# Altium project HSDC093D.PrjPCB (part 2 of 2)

## Sheet HSDC093D_720.SchDoc
size 431 x 279 mm; Date: Not shown in title block; ApprovedBy: Not shown in title block; CheckedBy: Not shown in title block; Author: Not shown in title block; CompanyName: Not shown in title block; Engineer: Not shown in title block; Organization: Not shown in title block; Address1: Not shown in title block; Address2: Not shown in title block; Address3: Not shown in title block; Address4: Not shown in title block; DocumentNumber: 2; Revision: Use project parameter SCH_Rev; SheetNumber: 2; SheetTotal: 5; PageSetup: Record=PageOptions¦CenterHorizontal=True¦CenterVertical=True¦PrintScale=1.00¦XCorrection=1.00¦YCorrection=1.00¦PrintKind=0¦BorderSize=5000000¦LeftOffset=0¦BottomOffset=0¦Orientation=2¦PaperLength=1000¦PaperWidth=1000¦Scale=100¦PaperSource=15¦PrintQuality=600¦MediaType=1¦DitherType=10¦PaperKind=Letter¦PrintScaleMode=1
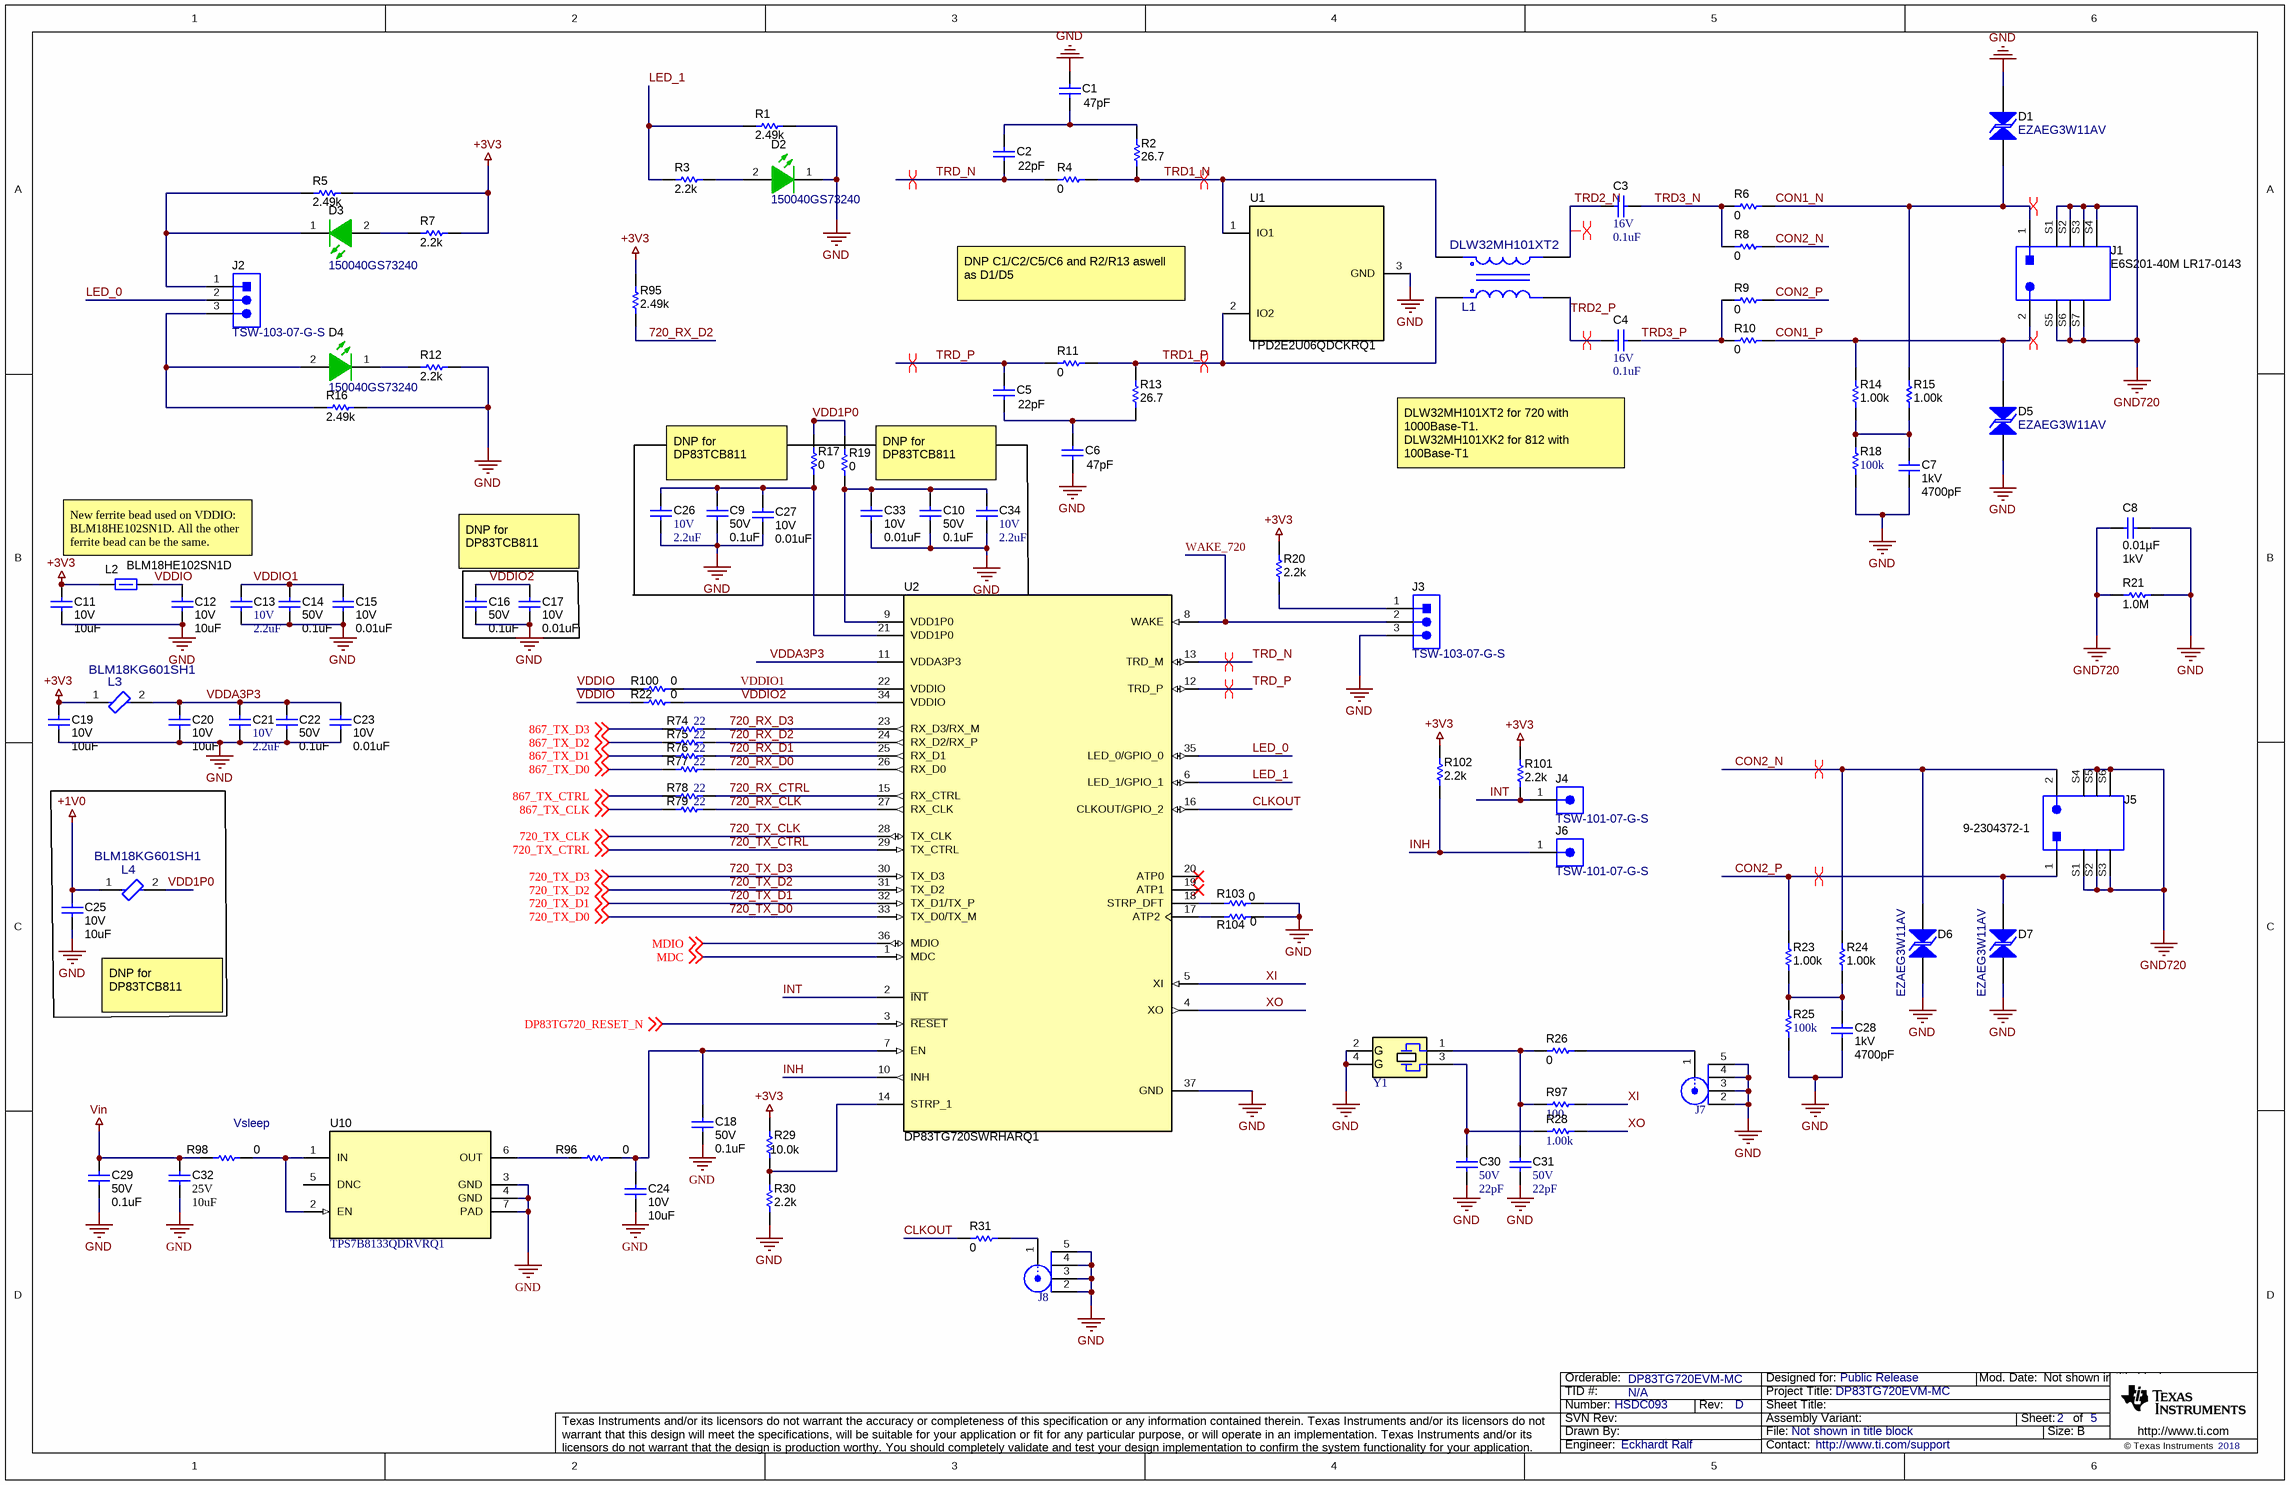
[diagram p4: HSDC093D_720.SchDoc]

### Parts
C1  ValueDisplayed: 47pF  [0402]  (hidden comment: GRM1555C1H470FA01D)
C2  ValueDisplayed: 22pF  [0402]  (hidden comment: GRM1555C1H220FA01D)
C3  VDC_V: 16V  ValueDisplayed: 0.1uF  [0402]  (hidden comment: 0402YC104KAT2A)
C4  VDC_V: 16V  ValueDisplayed: 0.1uF  [0402]  (hidden comment: 0402YC104KAT2A)
C5  ValueDisplayed: 22pF  [0402]  (hidden comment: GRM1555C1H220FA01D)
C6  ValueDisplayed: 47pF  [0402]  (hidden comment: GRM1555C1H470FA01D)
C7  VDC_V: 1kV  ValueDisplayed: 4700pF  [1206]  (hidden comment: GRM31BR73A472KW01L)
C8  ValueDisplayed: 0.01µF  VDC_V: 1kV  [1206]  (hidden comment: C1206X103KDRAC7800)
C9  VDC_V: 50V  ValueDisplayed: 0.1uF  [0402]  (hidden comment: C1005X5R1H104K050BB)
C10  VDC_V: 50V  ValueDisplayed: 0.1uF  [0402]  (hidden comment: C1005X5R1H104K050BB)
C11  VDC_V: 10V  ValueDisplayed: 10uF  [0402]  (hidden comment: GRM155R61A106ME11)
C12  VDC_V: 10V  ValueDisplayed: 10uF  [0402]  (hidden comment: GRM155R61A106ME11)
C13  VDC_V: 10V  ValueDisplayed: 2.2uF  [0402]  (hidden comment: C1005X5R1A225K050BC)
C14  VDC_V: 50V  ValueDisplayed: 0.1uF  [0402]  (hidden comment: C1005X5R1H104K050BB)
C15  VDC_V: 10V  ValueDisplayed: 0.01uF  [0402]  (hidden comment: GRM155R61A103KA01D)
C16  VDC_V: 50V  ValueDisplayed: 0.1uF  [0402]  (hidden comment: C1005X5R1H104K050BB)
C17  VDC_V: 10V  ValueDisplayed: 0.01uF  [0402]  (hidden comment: GRM155R61A103KA01D)
C18  VDC_V: 50V  ValueDisplayed: 0.1uF  [0402]  (hidden comment: C1005X5R1H104K050BB)
C19  VDC_V: 10V  ValueDisplayed: 10uF  [0402]  (hidden comment: GRM155R61A106ME11)
C20  VDC_V: 10V  ValueDisplayed: 10uF  [0402]  (hidden comment: GRM155R61A106ME11)
C21  VDC_V: 10V  ValueDisplayed: 2.2uF  [0402]  (hidden comment: C1005X5R1A225K050BC)
C22  VDC_V: 50V  ValueDisplayed: 0.1uF  [0402]  (hidden comment: C1005X5R1H104K050BB)
C23  VDC_V: 10V  ValueDisplayed: 0.01uF  [0402]  (hidden comment: GRM155R61A103KA01D)
C24  VDC_V: 10V  ValueDisplayed: 10uF  [0402]  (hidden comment: GRM155R61A106ME11)
C25  VDC_V: 10V  ValueDisplayed: 10uF  [0402]  (hidden comment: GRM155R61A106ME11)
C26  VDC_V: 10V  ValueDisplayed: 2.2uF  [0402]  (hidden comment: C1005X5R1A225K050BC)
C27  VDC_V: 10V  ValueDisplayed: 0.01uF  [0402]  (hidden comment: GRM155R61A103KA01D)
C28  VDC_V: 1kV  ValueDisplayed: 4700pF  [1206]  (hidden comment: GRM31BR73A472KW01L)
C29  VDC_V: 50V  ValueDisplayed: 0.1uF  [0402]  (hidden comment: C1005X5R1H104K050BB)
C30  VDC_V: 50V  ValueDisplayed: 22pF  [0402]  (hidden comment: GRM1555C1H220FA01D)
C31  VDC_V: 50V  ValueDisplayed: 22pF  [0402]  (hidden comment: GRM1555C1H220FA01D)
C32  VDC_V: 25V  ValueDisplayed: 10uF  [0603]  (hidden comment: C1608X5R1E106M080AC)
C33  VDC_V: 10V  ValueDisplayed: 0.01uF  [0402]  (hidden comment: GRM155R61A103KA01D)
C34  VDC_V: 10V  ValueDisplayed: 2.2uF  [0402]  (hidden comment: C1005X5R1A225K050BC)
D1  EZAEG3W11AV  [0603]
D2  150040GS73240  [WL-SMCC_0402_Green]
D3  150040GS73240  [WL-SMCC_0402_Green]
D4  150040GS73240  [WL-SMCC_0402_Green]
D5  EZAEG3W11AV  [0603]
D6  EZAEG3W11AV  [0603]
D7  EZAEG3W11AV  [0603]
J1  E6S201-40M LR17-0143  [Rosenberger_E6S201-40M_LR17-0143]
J2  TSW-103-07-G-S  [TSW-103-07-G-S]
J3  TSW-103-07-G-S  [TSW-103-07-G-S]
J4  TSW-101-07-G-S  [TSW-101-07-G-S]
J5  9-2304372-1  [TE_1PORT_B1-B]
J6  TSW-101-07-G-S  [TSW-101-07-G-S]
J7  901-144-8RFX  [AMPHENOL_901-144-8RFX]  (value not drawn)
J8  901-144-8RFX  [AMPHENOL_901-144-8RFX]  (value not drawn)
L1  DLW32MH101XT2  [FP-DLW32MH101XT2_1210-MFG]
L2  BLM18HE102SN1D  [0603]
L3  BLM18KG601SH1  [FP-BLM18KG601SH1_0603 (1608 Metric)-MFG]
L4  BLM18KG601SH1  [FP-BLM18KG601SH1_0603 (1608 Metric)-MFG]
R1  ValueDisplayed: 2.49k  [0402]  (hidden comment: CRCW04022K49FKED)
R2  ValueDisplayed: 26.7  [0402]  (hidden comment: CRCW040226R7FKED)
R3  ValueDisplayed: 2.2k  [0402]  (hidden comment: CRCW04022K20JNED)
R4  ValueDisplayed: 0  [0402]  (hidden comment: CRCW04020000Z0EDHP)
R5  ValueDisplayed: 2.49k  [0402]  (hidden comment: CRCW04022K49FKED)
R6  ValueDisplayed: 0  [0402]  (hidden comment: CRCW04020000Z0EDHP)
R7  ValueDisplayed: 2.2k  [0402]  (hidden comment: CRCW04022K20JNED)
R8  ValueDisplayed: 0  [0402]  (hidden comment: CRCW04020000Z0EDHP)
R9  ValueDisplayed: 0  [0402]  (hidden comment: CRCW04020000Z0EDHP)
R10  ValueDisplayed: 0  [0402]  (hidden comment: CRCW04020000Z0EDHP)
R11  ValueDisplayed: 0  [0402]  (hidden comment: CRCW04020000Z0EDHP)
R12  ValueDisplayed: 2.2k  [0402]  (hidden comment: CRCW04022K20JNED)
R13  ValueDisplayed: 26.7  [0402]  (hidden comment: CRCW040226R7FKED)
R14  ValueDisplayed: 1.00k  [0805_HV]  (hidden comment: ERJ-P06F1001V)
R15  ValueDisplayed: 1.00k  [0805_HV]  (hidden comment: ERJ-P06F1001V)
R16  ValueDisplayed: 2.49k  [0402]  (hidden comment: CRCW04022K49FKED)
R17  ValueDisplayed: 0  [0402]  (hidden comment: CRCW04020000Z0EDHP)
R18  ValueDisplayed: 100k  [0805_HV]  (hidden comment: CRCW08051M00JNEA)
R19  ValueDisplayed: 0  [0402]  (hidden comment: CRCW04020000Z0EDHP)
R20  ValueDisplayed: 2.2k  [0402]  (hidden comment: CRCW04022K20JNED)
R21  ValueDisplayed: 1.0M  [1206]  (hidden comment: CRCW12061M00JNEA)
R22  ValueDisplayed: 0  [0402]  (hidden comment: CRCW04020000Z0EDHP)
R23  ValueDisplayed: 1.00k  [0805_HV]  (hidden comment: ERJ-P06F1001V)
R24  ValueDisplayed: 1.00k  [0805_HV]  (hidden comment: ERJ-P06F1001V)
R25  ValueDisplayed: 100k  [0805_HV]  (hidden comment: CRCW08051M00JNEA)
R26  ValueDisplayed: 0  [0402]  (hidden comment: ERJ-2GE0R00X)
R28  ValueDisplayed: 1.00k  [0402]  (hidden comment: CRCW04021K00FKED)
R29  ValueDisplayed: 10.0k  [0402]  (hidden comment: RT0402BRD0710KL)
R30  ValueDisplayed: 2.2k  [0402]  (hidden comment: CRCW04022K20JNED)
R31  ValueDisplayed: 0  [0402]  (hidden comment: ERJ-2GE0R00X)
R74  ValueDisplayed: 22  [0402]  (hidden comment: CRCW040222R0JNED)
R75  ValueDisplayed: 22  [0402]  (hidden comment: CRCW040222R0JNED)
R76  ValueDisplayed: 22  [0402]  (hidden comment: CRCW040222R0JNED)
R77  ValueDisplayed: 22  [0402]  (hidden comment: CRCW040222R0JNED)
R78  ValueDisplayed: 22  [0402]  (hidden comment: CRCW040222R0JNED)
R79  ValueDisplayed: 22  [0402]  (hidden comment: CRCW040222R0JNED)
R95  ValueDisplayed: 2.49k  [0402]  (hidden comment: CRCW04022K49FKED)
R96  ValueDisplayed: 0  [0402]  (hidden comment: CRCW04020000Z0EDHP)
R97  ValueDisplayed: 100  [0402]  (hidden comment: CRCW0402100RFKED)
R98  ValueDisplayed: 0  [0402]  (hidden comment: CRCW04020000Z0EDHP)
R100  ValueDisplayed: 0  [0402]  (hidden comment: CRCW04020000Z0EDHP)
R101  ValueDisplayed: 2.2k  [0402]  (hidden comment: CRCW04022K20JNED)
R102  ValueDisplayed: 2.2k  [0402]  (hidden comment: CRCW04022K20JNED)
R103  ValueDisplayed: 0  [0402]  (hidden comment: ERJ-2GE0R00X)
R104  ValueDisplayed: 0  [0402]  (hidden comment: ERJ-2GE0R00X)
U1  TPD2E2U06QDCKRQ1  [DCK0003A_N]
U2  DP83TG720SWRHARQ1  [RND0036A]
U10  TPS7B8133QDRVRQ1  [DRV0006A]
Y1  ABM8AIG-25.000MHZ-12-2Z-T3  [Abracon_ABM8AIG]  (value not drawn)

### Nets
+1V0: C25.1 L4.1
+3V3: C11.1 C19.1 L2.1 L3.1 R5.2 R7.2 R20.2 R29.2 R95.2 R101.2 R102.1
GND: C1.1 C6.2 C7.2 C8.1 C9.2 C10.2 C11.2 C12.2 C13.2 C14.2 C15.2 C16.2 C17.2 C18.2 C19.2 C20.2 C21.2 C22.2 C23.2 C24.2 C25.2 C26.2 C27.2 C28.2 C29.2 C30.2 C31.2 C32.2 C33.2 C34.2 D1.2 D2.1(K) D5.1 D6.1 D7.1 J3.3 J7.2 J7.3 J7.4 J7.5 J8.2 J8.3 J8.4 J8.5 R1.2 R12.2 R16.2 R18.1 R21.2 R25.1 R30.2 R103.2 R104.2 U1.3(GND) U2.37(GND) U10.3(GND) U10.4(GND) U10.7(PAD) Y1.2(GND) Y1.4(GND)
GND720: C8.2 J1.S1 J1.S2 J1.S3 J1.S4 J1.S5 J1.S6 J1.S7 J5.S1(GND) J5.S2(GND) J5.S3(GND) J5.S4(GND) J5.S5(GND) J5.S6(GND) R21.1
Vin: C29.1 C32.1 R98.2
720_RX_CLK: R79.2 U2.27(RX_CLK)
720_RX_CTRL: R78.2 U2.15(RX_CTRL)
720_RX_D0: R77.2 U2.26(RX_D0)
720_RX_D1: R76.2 U2.25(RX_D1)
720_RX_D2: R75.2 R95.1 U2.24(RX_D2/RX_P)
720_RX_D3: R74.2 U2.23(RX_D3/RX_M)
720_TX_CLK: U2.28(TX_CLK) ; off-sheet 720_TX_CLK
720_TX_CTRL: U2.29(TX_CTRL) ; off-sheet 720_TX_CTRL
720_TX_D0: U2.33(TX_D0/TX_M) ; off-sheet 720_TX_D0
720_TX_D1: U2.32(TX_D1/TX_P) ; off-sheet 720_TX_D1
720_TX_D2: U2.31(TX_D2) ; off-sheet 720_TX_D2
720_TX_D3: U2.30(TX_D3) ; off-sheet 720_TX_D3
867_TX_CLK: R79.1 ; off-sheet 867_TX_CLK
867_TX_CTRL: R78.1 ; off-sheet 867_TX_CTRL
867_TX_D0: R77.1 ; off-sheet 867_TX_D0
867_TX_D1: R76.1 ; off-sheet 867_TX_D1
867_TX_D2: R75.1 ; off-sheet 867_TX_D2
867_TX_D3: R74.1 ; off-sheet 867_TX_D3
CLKOUT: R31.1 U2.16(CLKOUT/GPIO_2)
CON1_N: D1.1 J1.1 R6.2 R15.2
CON1_P: D5.2 J1.2 R10.2 R14.2
CON2_N: D6.2 J5.2 R8.2 R24.2
CON2_P: D7.2 J5.1 R9.2 R23.2
DP83TG720_RESET_N: U2.3(~{RESET}) ; off-sheet DP83TG720_RESET_N
INH: J6.1 R102.2 U2.10(INH)
INT: J4.1 R101.1 U2.2(~{INT})
LED_0: J2.2 U2.35(LED_0/GPIO_0)
LED_1: R1.1 R3.1 U2.6(LED_1/GPIO_1)
MDC: U2.1(MDC) ; off-sheet MDC
MDIO: U2.36(MDIO) ; off-sheet MDIO
TRD1_N: L1.4 R2.1 R4.1 U1.1(IO1)
TRD1_P: L1.1 R11.1 R13.2 U1.2(IO2)
TRD2_N: C3.2 L1.3
TRD2_P: C4.2 L1.2
TRD3_N: C3.1 R6.1 R8.1
TRD3_P: C4.1 R9.1 R10.1
TRD_N: C2.2 R4.2 U2.13(TRD_M)
TRD_P: C5.1 R11.2 U2.12(TRD_P)
VDD1P0: L4.2 R17.2 R19.2
VDDA3P3: C20.1 C21.1 C22.1 C23.1 L3.2 U2.11(VDDA3P3)
VDDIO: C12.1 L2.2 R22.2 R100.2
VDDIO1: C13.1 C14.1 C15.1 R100.1 U2.22(VDDIO)
VDDIO2: C16.1 C17.1 R22.1 U2.34(VDDIO)
WAKE_720: J3.2 U2.8(WAKE)
XI: R97.2 U2.5(XI)
XO: R28.2 U2.4(XO)
NetC1_2: C1.2 C2.1 R2.2
NetC5_2: C5.2 C6.1 R13.1
NetC7_1: C7.1 R14.1 R15.1 R18.2
NetC9_1: C9.1 C26.1 C27.1 R17.1 U2.21(VDD1P0)
NetC10_1: C10.1 C33.1 C34.1 R19.1 U2.9(VDD1P0)
NetC18_1: C18.1 C24.1 R96.1 U2.7(EN)
NetC28_1: C28.1 R23.1 R24.1 R25.2
NetC30_1: C30.1 R28.1 Y1.3
NetC31_1: C31.1 R26.1 R97.1 Y1.1
NetD2_2: D2.2(A) R3.2
NetD3_1: D3.1(K) J2.1 R5.1
NetD3_2: D3.2(A) R7.1
NetD4_1: D4.1(K) R12.1
NetD4_2: D4.2(A) J2.3 R16.1
NetJ3_1: J3.1 R20.1
NetJ7_1: J7.1 R26.2
NetJ8_1: J8.1 R31.2
NetR29_1: R29.1 R30.1 U2.14(STRP_1)
NetR96_2: R96.2 U10.6(OUT)
NetR98_1: R98.1 U10.1(IN) U10.2(EN)
NetR103_1: R103.1 U2.18(STRP_DFT)
NetR104_1: R104.1 U2.17(ATP2)

Not connected (* = marked no-connect by the designer): U2 19(ATP1)* 20(ATP0)*; U10 5(DNC)

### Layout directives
differential pair: CON1_N, CON1_P, CON2_N, CON2_P, TRD1_N, TRD1_P, TRD2_N, TRD2_P, TRD_N, TRD_P

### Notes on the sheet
- DNP C1/C2/C5/C6 and R2/R13 aswell as D1/D5
- DNP for DP83TCB811
- DLW32MH101XT2 for 720 with 1000Base-T1.
  DLW32MH101XK2 for 812 with
  100Base-T1
- New ferrite bead used on VDDIO: BLM18HE102SN1D. All the other ferrite bead can be the same.
- (near R98) Vsleep

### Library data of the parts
C1 C6 = CMP-0006467-2: CAP, CERM, 47 pF, 50 V, +/- 1%, C0G/NP0, 0402; Manufacturer: MuRata; TaMin_C: -55°C; Polarized: N; SizeAreaWB_mm2: 3; Value1: Unknown; U/M: EA; Value: 47pF; TaMax_C: 125°C; SizeZ_mm: 0.6; SizeX_mm: 1; SizeY_mm: 0.5; Value2: 50V; AEC Category: Q200
C2 C5 = CMP-0006438-2: CAP, CERM, 22 pF, 50 V, +/- 1%, C0G/NP0, 0402; Manufacturer: MuRata; TaMin_C: -55°C; Polarized: N; SizeAreaWB_mm2: 3; Value1: Unknown; U/M: EA; Value: 22pF; TaMax_C: 125°C; SizeZ_mm: 0.6; SizeX_mm: 1; SizeY_mm: 0.5; Value2: 50V; AEC Category: Q200
C3 C4 = CMP-0006201-2: CAP, CERM, 0.1 uF, 16 V, +/- 10%, X7R, 0402; Manufacturer: AVX; TaMin_C: -55°C; Polarized: N; SizeAreaWB_mm2: 3; Value1: Unknown; U/M: EA; Value: 0.1uF; TaMax_C: 125°C; SizeZ_mm: 0.6; SizeX_mm: 1; SizeY_mm: 0.5; Cap_F: 100nF; AEC Category: Q200
C7 C28 = CMP-0008920-2: CAP, CERM, 4700 pF, 1000 V, +/- 10%, X7R, 1206; Manufacturer: MuRata; TaMin_C: -55°C; Polarized: N; SizeAreaWB_mm2: 10.92; Value1: Unknown; U/M: EA; Value: 4700pF; TaMax_C: 125°C; SizeZ_mm: 1.35; SizeX_mm: 3.2; SizeY_mm: 1.6; Value2: 1000V; SizeArea_mm2: 5.12; Cap_F: 4.7nF; AEC Category: Q200
C8 = CMP-0085177-1: CAP, CERM, 0.01 µF, 1000 V,+/- 10%, X7R, 1206; Manufacturer: Kemet; SizeZ_mm: 1.35; SizeArea_mm2: 5.12; AEC Category: Q200; Cap_F: 10nF; U/M: EA; SizeY_mm: 1.6; SizeX_mm: 3.2; Value2: 1000V; TaMax_C: 125°C; Polarized: N; SizeAreaWB_mm2: 10.92; Value: 0.01uF; TaMin_C: -55°C
C9 C10 C14 C16 C18 C22 C29 = CMP-0006279-2: CAP, CERM, 0.1 uF, 50 V, +/- 10%, X5R, 0402; Manufacturer: TDK; TaMin_C: -55°C; ESR_ohm: 39.064m; Polarized: N; SizeAreaWB_mm2: 3; Value1: 0.039064 ohm; U/M: EA; Value: 0.1uF; TaMax_C: 85°C; SizeZ_mm: 0.6; SizeX_mm: 1; SizeY_mm: 0.5; Cap_F: 100nF; IRMS_A: 814.669mA; AEC Category: Q200
C11 C12 C19 C20 C24 C25 = CMP-0006564-2: CAP, CERM, 10 uF, 10 V, +/- 20%, X5R, 0402; Manufacturer: MuRata; TaMin_C: -55°C; Polarized: N; SizeAreaWB_mm2: 3; Value1: Unknown; U/M: EA; Value: 10uF; TaMax_C: 85°C; SizeZ_mm: 0.6; SizeX_mm: 1; SizeY_mm: 0.5; Cap_F: 10µF; AEC Category: Q200
C13 C21 C26 C34 = CMP-0006263-2: CAP, CERM, 2.2 uF, 10 V, +/- 10%, X5R, 0402; Manufacturer: TDK; TaMin_C: -55°C; Polarized: N; SizeAreaWB_mm2: 3; Value1: Unknown; U/M: EA; Value: 2.2uF; TaMax_C: 85°C; SizeZ_mm: 0.6; SizeX_mm: 1; SizeY_mm: 0.5; Cap_F: 2.2µF; AEC Category: Q200
C15 C17 C23 C27 C33 = CMP-0006561-2: CAP, CERM, 0.01 uF, 10 V, +/- 10%, X5R, 0402; Manufacturer: MuRata; TaMin_C: -55°C; Polarized: N; SizeAreaWB_mm2: 3; Value1: Unknown; U/M: EA; Value: 0.01uF; TaMax_C: 85°C; SizeZ_mm: 0.6; SizeX_mm: 1; SizeY_mm: 0.5; Cap_F: 10nF; AEC Category: Q200
C30 C31 = CMP-0006438-2: CAP, CERM, 22 pF, 50 V, +/- 1%, C0G/NP0, 0402; Manufacturer: MuRata; TaMin_C: -55°C; Polarized: N; SizeAreaWB_mm2: 3; Value1: Unknown; U/M: EA; Value: 22pF; TaMax_C: 125°C; SizeZ_mm: 0.6; SizeX_mm: 1; SizeY_mm: 0.5; AEC Category: Q200
C32 = CMP-0007007-5: CAP, CERM, 10 uF, 25 V, +/- 20%, X5R, 0603; Manufacturer: TDK; TaMin_C: -55°C; ESR_ohm: 4.639m; Polarized: N; SizeAreaWB_mm2: 4.68; Value1: 0.004639 ohm; U/M: EA; Value: 10uF; TaMax_C: 85°C; SizeZ_mm: 1; SizeX_mm: 1.6; SizeY_mm: 0.8; SizeArea_mm2: 1.28; Cap_F: 10µF; IRMS_A: 2.41407A; AEC Category: Q200
D1 D5-D7 = CMP-0086344-1: Diode, TVS, Bi, AEC-Q101, 0603; Manufacturer: Panasonic; SizeX_mm: 1.6; AEC Qualified: Y; SizeArea_mm2: 1.28; SizeY_mm: 0.8; SizeAreaWB_mm2: 4.68; AEC Category: Q101; SizeZ_mm: 1
D2-D4 = CMP-0081765-2: LED, Green, SMD; Manufacturer: Wurth Elektronik; Vr_V: 5V; Io_A: 20mA; Tjmax_C: 95°C; Ir_A: 10µA; Power_TotalModule: 99mW; Value2: 3.2V; SizeArea_mm2: 0.5; SizeX_mm: 1; Value1: 0.099W; Angle: 120; Type: InGaN; SizeAreaWB_mm2: 3
J1 = CMP-0084194-1: Connector, 2 Pos, TH; Manufacturer: Rosenberger; CompType: Plug; Gender: Male; Current_A: 500mA; Voltage_V: 50V
J2 J3 = CMP-0075407-2: Header, 100mil, 3x1, Gold, TH; Manufacturer: Samtec; Pitch_mm: 2.54; Cert_VDE: N; Gender: Male; Cert_CSA: Y; Voltage_V: 550V; Green_REACh: Passed; Current_A: 6.3A; Green_Lifecycle: Active; Row_Count: 1
J4 J6 = CMP-0075403-1: Header, 100mil, 1pos, Gold, TH; Manufacturer: Samtec; Pitch_mm: 2.54; Cert_VDE: N; Gender: Male; Cert_CSA: Y; Voltage_V: 550V; Green_REACh: Passed; Current_A: 6.3A; CT: False; Green_Lifecycle: Active; Row_Count: 1; CNHeader: True
J5 = CMP-0054903-1: Header(shrouded), 2x1, R/A, TH; Manufacturer: TE Connectivity; Gender: Male; Pitch_mm: 1.8; CT: FALSE; Row_Count: 1; Shrouded: Y
J7 J8 = CMP-0055833-1: SMA Straight Jack, Gold, 50 Ohm, TH; Manufacturer: Amphenol RF; CNHeader: FALSE; Green_Lifecycle: Not Set; Green_REACh: Incomplete; CT: TRUE
L1 = CMP-0090833-1: 100μH @ 100kHz 2 Line Common Mode Choke Surface Mount 100mA DCR 3.12Ω; Manufacturer: Murata; AEC Qualified: Yes; SizeZ_mm: 2.5mm; DCR_ohm: 3.12; AEC Grade: Grade 1; Tolerance_%: -25/+50%
L2 = CMP-0003348-2: Ferrite Bead, 1000 ohm @ 100 MHz, 0.6 A, 0603; Manufacturer: MuRata; Ztyp@1GHz_Ohm: 1k; SizeAreaWB_mm2: 4.68; DCR_ohm: 3.5d; Value1: 0.35 ohm; Imax_A: 6dA; SizeZ_mm: 1; SizeX_mm: 1.6; SizeY_mm: 0.8; Value2: 0.6A; SizeArea_mm2: 1.28
L3 L4 = CMP-0089848-1: 600 Ohms @ 100MHz 1 Power Line Ferrite Bead 0603 (1608 Metric) 1.3A 150mOhm; Manufacturer: Murata; Tolerance_%: 25%; SizeZ_mm: 0.95mm; Impedance At Frequency: 600Ω @ 100MHz; AEC Qualified: Yes; AEC Grade: Grade 1; DCR_ohm: 0.15
R1 R5 R16 R95 = CMP-0026237-2: RES, 2.49 k, 1%, 0.063 W, AEC-Q200 Grade 0, 0402; Manufacturer: Vishay-Dale; Power_W: 63mW; TempCo: 100 ppm/C; Value_Code: 2k49; Value: 2.49k; EIA_Code: E96; SizeX_mm: 1; SizeY_mm: 0.5; SizeZ_mm: 0.6; Value2: 0.063W; AEC Qualified: Y; VDC_V: 50V; AEC Category: Q200; AEC Grade: 0
R2 R13 = CMP-0026210-2: RES, 26.7, 1%, 0.063 W, AEC-Q200 Grade 0, 0402; Manufacturer: Vishay-Dale; Power_W: 63mW; TempCo: 100 ppm/C; Value_Code: 26R7; Value: 26.7; SizeX_mm: 1; SizeY_mm: 0.5; SizeZ_mm: 0.6; Value2: 0.063W; AEC Qualified: Y; VDC_V: 50V; AEC Grade: 0; AEC Category: Q200; EIA_Code: E96
R3 R7 R12 R20 R101 R102 = CMP-0026890-5: RES, 2.2 k, 5%, 0.063 W, AEC-Q200 Grade 0, 0402; Manufacturer: Vishay-Dale; Power_W: 63mW; TempCo: 200 ppm/C; Value_Code: 2k20; Value: 2.2k; EIA_Code: E24; SizeX_mm: 1; SizeY_mm: 0.5; SizeZ_mm: 0.6; Value2: 0.063W; AEC Qualified: Y; VDC_V: 50V; AEC Category: Q200; AEC Grade: 0
R4 R6 R8-R11 R17 R19 R22 R96 R98 R100 = CMP-0081856-1: RES, 0, 0%, 0.2 W, AEC-Q200 Grade 0, 0402; Manufacturer: Vishay-Dale; SizeAreaWB_mm2: 3; SizeArea_mm2: 0.5; AEC Qualified: Y; AEC Category: Q200; Value: 0; SizeZ_mm: 0.6; Power_W: 200mW; VDC_V: 50V; Value2: 0.2W; SizeX_mm: 1
R14 R15 R23 R24 = CMP-0021848-2: RES, 1.00 k, 1%, 0.25 W, 0805; Manufacturer: Panasonic; Power_W: 250mW; TempCo: 100 ppm/C; Value_Code: 1k00; U/M: EA; Value: 1.00k; EIA_Code: E96; Res_ohm: 1k; SizeX_mm: 2; SizeY_mm: 1.25; SizeZ_mm: 1.45; Value2: 0.25W; SizeArea_mm2: 2.5; VDC_V: 400V; AEC Category: Q200
R18 R25 = CMP-0020834-3: RES, 100 k, 1%, 0.125 W, AEC-Q200 Grade 0, 0805; Manufacturer: Vishay-Dale; PartNumber: CRCW0805100KFKEA; Power_W: 125mW; TempCo: 100 ppm/C; Value: 100k; EIA_Code: E96; SizeX_mm: 2; SizeY_mm: 1.25; SizeZ_mm: 1.45; Value2: 0.125W; SizeArea_mm2: 2.5; AEC Qualified: Y; VDC_V: 150V; AEC Category: Q200; AEC Grade: 0
R21 = CMP-0018610-3: RES, 1.0 M, 5%, 0.25 W, AEC-Q200 Grade 0, 1206; Manufacturer: Vishay-Dale; Power_W: 250mW; TempCo: 200 ppm/C; Value_Code: 1M00; Value: 1.0Meg; EIA_Code: E24; Res_ohm: 1M; SizeX_mm: 3.2; SizeY_mm: 1.6; SizeZ_mm: 1.35; Value2: 0.25W; SizeArea_mm2: 5.12; AEC Qualified: Y; VDC_V: 200V; AEC Category: Q200; AEC Grade: 0
R26 R31 R103 R104 = CMP-0026992-3: RES, 0, 5%, 0.1 W, AEC-Q200 Grade 0, 0402; Manufacturer: Panasonic; Power_W: 100mW; TempCo: 600 ppm/C; Value_Code: 0000; Value: 0; EIA_Code: E24; SizeX_mm: 1; SizeY_mm: 0.5; SizeZ_mm: 0.6; Value2: 0.1W; AEC Qualified: Y; AEC Category: Q200; VDC_V: 50V; SizeAreaWB_mm2: 3
R28 = CMP-0026071-3: RES, 1.00 k, 1%, 0.063 W, AEC-Q200 Grade 0, 0402; Manufacturer: Vishay-Dale; Power_W: 63mW; TempCo: 100 ppm/C; Value_Code: 1k00; Value: 1.00k; EIA_Code: E96; Res_ohm: 1k; SizeX_mm: 1; SizeY_mm: 0.5; SizeZ_mm: 0.6; Value2: 0.063W; AEC Qualified: Y; VDC_V: 50V; AEC Category: Q200; AEC Grade: 0
R29 = CMP-0065360-1: RES, 10.0 k, .1%, .0625 W, 0402; Manufacturer: Yageo America; Power_W: 62.5mW; TempCo: 25 ppm/C; Value_Code: 10k0; U/M: EA; Value: 10.0k; EIA_Code: E192; Tolerance_%: 0.1%; Res_ohm: 10k; SizeX_mm: 1.0; SizeY_mm: 0.5; SizeZ_mm: 0.6; Value2: .0625W; VDC_V: 50V; AEC Category: Q200
R30 = CMP-0026890-5: RES, 2.2 k, 5%, 0.063 W, AEC-Q200 Grade 0, 0402; Manufacturer: Vishay-Dale; Power_W: 63mW; TempCo: 200 ppm/C; Value_Code: 2k20; Value: 2.2k; SizeX_mm: 1; SizeY_mm: 0.5; SizeZ_mm: 0.6; Value2: 0.063W; AEC Qualified: Y; AEC Grade: 0; AEC Category: Q200; EIA_Code: E24; VDC_V: 50V
R74-R79 = CMP-0026880-3: RES, 22, 5%, 0.063 W, AEC-Q200 Grade 0, 0402; Manufacturer: Vishay-Dale; Power_W: 63mW; TempCo: 200 ppm/C; Value_Code: 22R0; Value: 22; EIA_Code: E24; SizeX_mm: 1; SizeY_mm: 0.5; SizeZ_mm: 0.6; Value2: 0.063W; AEC Qualified: Y; VDC_V: 50V; AEC Category: Q200; AEC Grade: 0
R97 = CMP-0025951-3: RES, 100, 1%, 0.063 W, AEC-Q200 Grade 0, 0402; Manufacturer: Vishay-Dale; Power_W: 63mW; TempCo: 100 ppm/C; Value_Code: 100R; Value: 100; EIA_Code: E96; SizeX_mm: 1; SizeY_mm: 0.5; SizeZ_mm: 0.6; Value2: 0.063W; AEC Qualified: Y; VDC_V: 50V; AEC Category: Q200; AEC Grade: 0
U1 = CMP-0073595-1: Automotive Dual-Channel High-Speed ESD Protection Device, DCK0003A (SOT-SC70-3); Alternate Manufacturer: Texas Instruments; SizeAreaWB_mm2: 9.3; U/M: EA; SizeZ_mm: 1.1; SizeX_mm: 2.1; SizeY_mm: 2.0; SizeArea_mm2: 4.2; CompType: IC
U2 = CMP-0085268-1: Low Power Auto PHY 1000BASE-T1 Automotive Ethernet Physical Layer Transceiver, RND0036A (VQFNP-36); Alternate Manufacturer: Texas Instruments; SizeY_mm: 6; SizeAreaWB_mm2: 64; SizeZ_mm: 0.9; AEC Qualified: Y; SizeArea_mm2: 36; AEC Category: Q200; CompType: IC
U10 = CMP-0860463-1: Automotive 150-mA high-voltage ultra-low-IQ low-dropout (LDO) linear regulator, DRV0006A (WSON-6); Alternate Manufacturer: Texas Instruments; AEC Qualified: Y; SizeY_mm: 2; SizeZ_mm: 0.8; AEC Category: Q200; CompType: IC; SizeArea_mm2: 4; SizeAreaWB_mm2: 9
Y1 = CMP-0004682-5: Crystal, 25 MHz, 12pF, AEC-Q200 Grade 1, SMD; Manufacturer: Abracon Corporation; TaMin_C: -40°C; Frequency Stability: 50 ppm; SizeAreaWB_mm2: 14.7; Frequency_Fixed: 25MHz; TaMax_C: 125°C; SizeZ_mm: 0.8; SizeX_mm: 2.5; SizeY_mm: 3.2; SizeArea_mm2: 8; AEC Category: Q200; AEC Grade: 1; AEC Qualified: Y

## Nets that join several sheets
+1V0: HSDC093D_Power_Sup (J21.1 R62.2), HSDC093D_720 (C25.1 L4.1)
+1V0_REG: HSDC093D_Power_Sup (6 pins), HSDC093D_867 (L5.1)
+2V5_REG: HSDC093D_Power_Sup (8 pins), HSDC093D_867 (L7.1)
+3V3: HSDC093D_Power_Sup (J20.1 R69.1), HSDC093D_720 (11 pins)
+3V3_REG: HSDC093D_Power_Sup (9 pins), HSDC093D_Controller (20 pins), HSDC093D_867 (L6.2 R94.2)
GND: HSDC093D_Power_Sup (30 pins), HSDC093D_Controller (44 pins), HSDC093D_867 (36 pins), HSDC093D_720 (60 pins)
Vin: HSDC093D_Power_Sup (12 pins), HSDC093D_Controller (C69.1 D11.1), HSDC093D_720 (C29.1 C32.1 R98.2)
720_TX_CLK: HSDC093D_867 (R81.1), HSDC093D_720 (U2.28)
720_TX_CTRL: HSDC093D_867 (R80.1), HSDC093D_720 (U2.29)
720_TX_D0: HSDC093D_867 (R82.1), HSDC093D_720 (U2.33)
720_TX_D1: HSDC093D_867 (R83.1), HSDC093D_720 (U2.32)
720_TX_D2: HSDC093D_867 (R84.1), HSDC093D_720 (U2.31)
720_TX_D3: HSDC093D_867 (R85.1), HSDC093D_720 (U2.30)
867_TX_CLK: HSDC093D_867 (U3.29), HSDC093D_720 (R79.1)
867_TX_CTRL: HSDC093D_867 (U3.37), HSDC093D_720 (R78.1)
867_TX_D0: HSDC093D_867 (U3.28), HSDC093D_720 (R77.1)
867_TX_D1: HSDC093D_867 (U3.27), HSDC093D_720 (R76.1)
867_TX_D2: HSDC093D_867 (U3.26), HSDC093D_720 (R75.1)
867_TX_D3: HSDC093D_867 (U3.25), HSDC093D_720 (R74.1)
83867_RESET_N: HSDC093D_Controller (R56.2), HSDC093D_867 (U3.43)
DP83TG720_RESET_N: HSDC093D_Controller (R58.2 U4.35), HSDC093D_720 (U2.3)
INH: HSDC093D_Controller (U4.37), HSDC093D_720 (J6.1 R102.2 U2.10)
INT: HSDC093D_Controller (U4.34), HSDC093D_720 (J4.1 R101.1 U2.2)
MDC: HSDC093D_Controller (J14.3), HSDC093D_867 (U3.16), HSDC093D_720 (U2.1)
MDIO: HSDC093D_Controller (J14.1 R45.1), HSDC093D_867 (U3.17), HSDC093D_720 (U2.36)
WAKE_720: HSDC093D_Controller (U4.36), HSDC093D_720 (J3.2 U2.8)

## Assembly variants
001: not fitted C1 C2 C5 C6 C12 C20 D1 D5 D6 D7 J1 R2 R6 R10 R13 R30 R91 R93 R103 R104 U1 U9
002: not fitted C28 C29 C30 C31 R26 U5
003: not fitted C1 C2 C5 C6 D1 D5 D6 D7 J1 R2 R6 R10 R13 R17 R19 R30 R91 R93 U1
